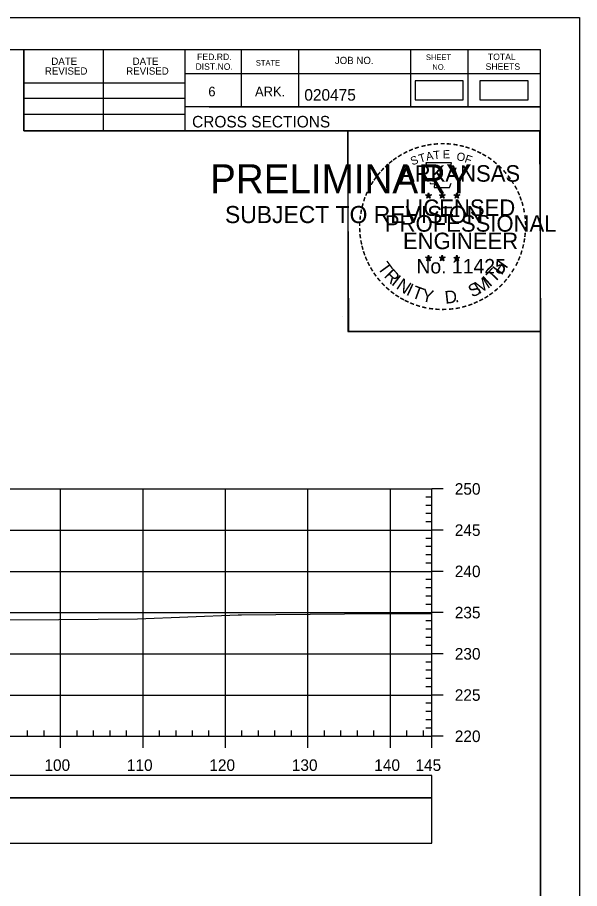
# Model space of a CAD drawing. Extents: x 1386544 to 1388153, y 379785 to 390999.
# Drawn here: x 1388085 to 1388153.2, y 384145.4 to 384251 of the extents above; entities that cross this region are included whole.
import ezdxf

# ---------------------------------------------------------------- set-up
doc = ezdxf.new("R2010")
doc.units = 0
for name, color, linetype in [('R_Axis', 7, 'Continuous'), ('R_Axis Annot', 7, 'Continuous'), ('R_Border', 7, 'Continuous'), ('R_Border PE', 7, 'Continuous'), ('R_Border Prem', 7, 'Continuous'), ('R_Exist Surface', 7, 'Continuous'), ('R_Grid', 7, 'Continuous'), ('R_No Plot', 7, 'Continuous'), ('S_SHOULDER', 7, 'Continuous')]:
    doc.layers.add(name, color=color, linetype=linetype)

msp = doc.modelspace()

# ---------------------------------------------------------------- linework, layer by layer
at = {"layer": 'R_Axis'}
for p, q in [((1388135.25, 384163.84), (1388135.25, 384193.84)), ((1388136.65, 384193.84), (1388135.25, 384193.84)), ((1388135.25, 384192.84), (1388134.55, 384192.84)), ((1388135.25, 384191.84), (1388134.55, 384191.84)), ((1388135.25, 384190.84), (1388134.55, 384190.84)), ((1388135.25, 384189.84), (1388134.55, 384189.84)), ((1388136.65, 384188.84), (1388135.25, 384188.84)), ((1388135.25, 384187.84), (1388134.55, 384187.84)), ((1388135.25, 384186.84), (1388134.55, 384186.84)), ((1388135.25, 384185.84), (1388134.55, 384185.84)), ((1388135.25, 384184.84), (1388134.55, 384184.84)), ((1388136.65, 384183.84), (1388135.25, 384183.84)), ((1388135.25, 384182.84), (1388134.55, 384182.84)), ((1388135.25, 384181.84), (1388134.55, 384181.84)), ((1388135.25, 384180.84), (1388134.55, 384180.84)), ((1388135.25, 384179.84), (1388134.55, 384179.84)), ((1388136.65, 384178.84), (1388135.25, 384178.84)), ((1388135.25, 384177.84), (1388134.55, 384177.84)), ((1388135.25, 384176.84), (1388134.55, 384176.84)), ((1388135.25, 384175.84), (1388134.55, 384175.84)), ((1388135.25, 384174.84), (1388134.55, 384174.84)), ((1388136.65, 384173.84), (1388135.25, 384173.84)), ((1388135.25, 384172.84), (1388134.55, 384172.84)), ((1388135.25, 384171.84), (1388134.55, 384171.84)), ((1388135.25, 384170.84), (1388134.55, 384170.84)), ((1388135.25, 384169.84), (1388134.55, 384169.84)), ((1388136.65, 384168.84), (1388135.25, 384168.84)), ((1388135.25, 384167.84), (1388134.55, 384167.84)), ((1388135.25, 384166.84), (1388134.55, 384166.84)), ((1388135.25, 384165.84), (1388134.55, 384165.84)), ((1388086.25, 384163.84), (1388086.25, 384164.54)), ((1388088.25, 384163.84), (1388088.25, 384164.54)), ((1388092.25, 384163.84), (1388092.25, 384164.54)), ((1388094.25, 384163.84), (1388094.25, 384164.54)), ((1388096.25, 384163.84), (1388096.25, 384164.54)), ((1388098.25, 384163.84), (1388098.25, 384164.54)), ((1388102.25, 384163.84), (1388102.25, 384164.54)), ((1388104.25, 384163.84), (1388104.25, 384164.54)), ((1388106.25, 384163.84), (1388106.25, 384164.54)), ((1388108.25, 384163.84), (1388108.25, 384164.54)), ((1388112.25, 384163.84), (1388112.25, 384164.54)), ((1388114.25, 384163.84), (1388114.25, 384164.54)), ((1388116.25, 384163.84), (1388116.25, 384164.54)), ((1388118.25, 384163.84), (1388118.25, 384164.54)), ((1388122.25, 384163.84), (1388122.25, 384164.54)), ((1388124.25, 384163.84), (1388124.25, 384164.54)), ((1388126.25, 384163.84), (1388126.25, 384164.54)), ((1388128.25, 384163.84), (1388128.25, 384164.54)), ((1388132.25, 384163.84), (1388132.25, 384164.54)), ((1388134.25, 384163.84), (1388134.25, 384164.54)), ((1388135.25, 384164.84), (1388134.55, 384164.84)), ((1387845.25, 384163.84), (1388135.25, 384163.84)), ((1388090.25, 384162.44), (1388090.25, 384163.84)), ((1388100.25, 384162.44), (1388100.25, 384163.84)), ((1388110.25, 384162.44), (1388110.25, 384163.84)), ((1388120.25, 384162.44), (1388120.25, 384163.84)), ((1388130.25, 384162.44), (1388130.25, 384163.84)), ((1388135.25, 384162.44), (1388135.25, 384163.84)), ((1388136.65, 384163.84), (1388135.25, 384163.84))]:
    msp.add_line(p, q, dxfattribs=at)
at = {"layer": 'R_Axis Annot'}
for points in [[(1388064.27, 384156.39), (1388135.25, 384156.39), (1388135.25, 384159.1), (1388064.27, 384159.1)], [(1388064.27, 384150.87), (1388135.25, 384150.87), (1388135.25, 384156.39), (1388064.27, 384156.39)]]:
    msp.add_lwpolyline(points, close=True, dxfattribs=at)
at = {"layer": 'R_Border'}
for p, q in [((1387832.25, 384247.13), (1388148.43, 384247.13)), ((1388085.79, 384237.25), (1388085.79, 384247.13)), ((1388095.47, 384237.25), (1388095.47, 384247.13)), ((1388105.33, 384247.13), (1388105.33, 384237.25)), ((1388112.17, 384247.13), (1388112.17, 384240.19)), ((1388119.11, 384247.13), (1388119.11, 384240.19)), ((1388132.69, 384247.13), (1388132.69, 384240.19)), ((1388139.63, 384247.13), (1388139.63, 384240.19)), ((1388148.43, 384041.67), (1388148.43, 384247.13)), ((1388148.43, 384244.19), (1388105.33, 384244.19)), ((1388148.43, 384244.21), (1388148.43, 384244.21)), ((1388085.79, 384243.11), (1388105.33, 384243.11)), ((1388085.79, 384241.25), (1388105.33, 384241.25)), ((1388148.43, 384240.19), (1388105.33, 384240.19)), ((1388108.29, 384240.19), (1388148.43, 384240.19)), ((1388085.79, 384239.31), (1388105.33, 384239.31)), ((1388148.43, 384237.25), (1388085.79, 384237.25))]:
    msp.add_line(p, q, dxfattribs=at)
at = {"layer": 'R_Border PE'}
for p, q in [((1388134.52, 384229.51), (1388134.87, 384229.39)), ((1388134.52, 384229.51), (1388134.77, 384229.46)), ((1388134.52, 384229.51), (1388134.75, 384229.38)), ((1388134.65, 384229.1), (1388134.87, 384229.39)), ((1388134.65, 384229.1), (1388134.78, 384229.34)), ((1388134.65, 384229.1), (1388134.86, 384229.31)), ((1388134.87, 384229.76), (1388134.82, 384229.51)), ((1388135.08, 384229.1), (1388134.86, 384229.31)), ((1388134.87, 384229.39), (1388134.87, 384229.76)), ((1388134.87, 384229.76), (1388134.91, 384229.51)), ((1388135.21, 384229.51), (1388134.87, 384229.39)), ((1388135.08, 384229.1), (1388134.87, 384229.39)), ((1388135.21, 384229.51), (1388134.93, 384229.46)), ((1388135.08, 384229.1), (1388134.94, 384229.39)), ((1388135.21, 384229.51), (1388135.01, 384229.4)), ((1388136.19, 384229.51), (1388136.54, 384229.39)), ((1388136.19, 384229.51), (1388136.44, 384229.46)), ((1388136.19, 384229.51), (1388136.42, 384229.38)), ((1388136.32, 384229.1), (1388136.54, 384229.39)), ((1388136.32, 384229.1), (1388136.45, 384229.34)), ((1388136.32, 384229.1), (1388136.53, 384229.31)), ((1388136.54, 384229.76), (1388136.49, 384229.51)), ((1388136.75, 384229.1), (1388136.53, 384229.31)), ((1388136.54, 384229.39), (1388136.54, 384229.76)), ((1388136.54, 384229.76), (1388136.58, 384229.51)), ((1388136.88, 384229.51), (1388136.54, 384229.39)), ((1388136.75, 384229.1), (1388136.54, 384229.39)), ((1388136.88, 384229.51), (1388136.6, 384229.46)), ((1388136.75, 384229.1), (1388136.61, 384229.39)), ((1388136.88, 384229.51), (1388136.68, 384229.4)), ((1388137.95, 384229.49), (1388138.3, 384229.38)), ((1388137.95, 384229.49), (1388138.2, 384229.45)), ((1388137.95, 384229.49), (1388138.19, 384229.37)), ((1388138.08, 384229.09), (1388138.3, 384229.38)), ((1388138.08, 384229.09), (1388138.21, 384229.33)), ((1388138.08, 384229.09), (1388138.3, 384229.3)), ((1388138.3, 384229.75), (1388138.26, 384229.5)), ((1388138.3, 384229.38), (1388138.3, 384229.75)), ((1388138.3, 384229.75), (1388138.35, 384229.5)), ((1388138.65, 384229.49), (1388138.3, 384229.38)), ((1388138.51, 384229.09), (1388138.3, 384229.38)), ((1388138.51, 384229.09), (1388138.3, 384229.3)), ((1388138.65, 384229.49), (1388138.36, 384229.44)), ((1388138.51, 384229.09), (1388138.38, 384229.38)), ((1388138.65, 384229.49), (1388138.44, 384229.39)), ((1388134.51, 384221.93), (1388134.86, 384221.82)), ((1388134.51, 384221.93), (1388134.77, 384221.89)), ((1388134.51, 384221.93), (1388134.75, 384221.81)), ((1388134.65, 384221.52), (1388134.86, 384221.82)), ((1388134.65, 384221.52), (1388134.77, 384221.77)), ((1388134.65, 384221.52), (1388134.86, 384221.74)), ((1388134.86, 384222.19), (1388134.82, 384221.93)), ((1388134.86, 384221.82), (1388134.86, 384222.19)), ((1388134.86, 384222.19), (1388134.91, 384221.94)), ((1388135.21, 384221.93), (1388134.86, 384221.82)), ((1388135.07, 384221.52), (1388134.86, 384221.82)), ((1388135.07, 384221.52), (1388134.86, 384221.74)), ((1388135.21, 384221.93), (1388134.92, 384221.88)), ((1388135.07, 384221.52), (1388134.94, 384221.82)), ((1388135.21, 384221.93), (1388135, 384221.83)), ((1388136.18, 384221.93), (1388136.53, 384221.82)), ((1388136.18, 384221.93), (1388136.43, 384221.89)), ((1388136.18, 384221.93), (1388136.42, 384221.81)), ((1388136.31, 384221.52), (1388136.53, 384221.82)), ((1388136.31, 384221.52), (1388136.44, 384221.77)), ((1388136.31, 384221.52), (1388136.53, 384221.74)), ((1388136.53, 384222.19), (1388136.49, 384221.93)), ((1388136.53, 384221.82), (1388136.53, 384222.19)), ((1388136.53, 384222.19), (1388136.58, 384221.94)), ((1388136.88, 384221.93), (1388136.53, 384221.82)), ((1388136.74, 384221.52), (1388136.53, 384221.82)), ((1388136.74, 384221.52), (1388136.53, 384221.74)), ((1388136.88, 384221.93), (1388136.59, 384221.88)), ((1388136.74, 384221.52), (1388136.61, 384221.82)), ((1388136.88, 384221.93), (1388136.67, 384221.83)), ((1388137.95, 384221.92), (1388138.3, 384221.81)), ((1388137.95, 384221.92), (1388138.2, 384221.88)), ((1388137.95, 384221.92), (1388138.19, 384221.8)), ((1388138.08, 384221.51), (1388138.3, 384221.81)), ((1388138.08, 384221.51), (1388138.21, 384221.76)), ((1388138.08, 384221.51), (1388138.3, 384221.73)), ((1388138.3, 384222.18), (1388138.26, 384221.92)), ((1388138.3, 384221.81), (1388138.3, 384222.18)), ((1388138.3, 384222.18), (1388138.35, 384221.93)), ((1388138.64, 384221.92), (1388138.3, 384221.81)), ((1388138.51, 384221.51), (1388138.3, 384221.81)), ((1388138.51, 384221.51), (1388138.3, 384221.73)), ((1388138.64, 384221.92), (1388138.36, 384221.87)), ((1388138.51, 384221.51), (1388138.37, 384221.81)), ((1388138.64, 384221.92), (1388138.44, 384221.82))]:
    msp.add_line(p, q, dxfattribs=at)
for points in [[(1388134.56, 384233.38), (1388134.83, 384232.56)], [(1388138.07, 384232.46), (1388138.21, 384232.75), (1388137.53, 384232.72), (1388137.67, 384233.38), (1388134.56, 384233.38)], [(1388135.05, 384230.96), (1388135.05, 384230.87), (1388135.61, 384230.85), (1388135.56, 384230.38), (1388137.43, 384230.38), (1388137.63, 384230.92)], [(1388134.87, 384229.76), (1388135.08, 384229.1), (1388134.52, 384229.51), (1388135.21, 384229.51), (1388134.65, 384229.1), (1388134.87, 384229.76)], [(1388136.54, 384229.76), (1388136.75, 384229.1), (1388136.19, 384229.51), (1388136.88, 384229.51), (1388136.32, 384229.1), (1388136.54, 384229.76)], [(1388138.3, 384229.75), (1388138.51, 384229.09), (1388137.95, 384229.49), (1388138.65, 384229.49), (1388138.08, 384229.09), (1388138.3, 384229.75)], [(1388134.86, 384222.19), (1388135.07, 384221.52), (1388134.51, 384221.93), (1388135.21, 384221.93), (1388134.65, 384221.52), (1388134.86, 384222.19)], [(1388136.53, 384222.19), (1388136.74, 384221.52), (1388136.18, 384221.93), (1388136.88, 384221.93), (1388136.31, 384221.52), (1388136.53, 384222.19)], [(1388138.3, 384222.18), (1388138.51, 384221.51), (1388137.95, 384221.92), (1388138.64, 384221.92), (1388138.08, 384221.51), (1388138.3, 384222.18)]]:
    msp.add_lwpolyline(points, dxfattribs=at)
for centre, radius in [((1388134.86, 384229.39), 0.172), ((1388134.86, 384229.39), 0.145), ((1388134.86, 384229.39), 0.116), ((1388134.86, 384229.39), 0.0991), ((1388134.86, 384229.39), 0.0747), ((1388134.86, 384229.39), 0.0495), ((1388134.86, 384229.39), 0.0296), ((1388136.53, 384229.39), 0.172), ((1388136.53, 384229.39), 0.145), ((1388136.53, 384229.39), 0.116), ((1388136.53, 384229.39), 0.0991), ((1388136.53, 384229.39), 0.0747), ((1388136.53, 384229.39), 0.0495), ((1388136.53, 384229.39), 0.0296), ((1388138.3, 384229.38), 0.172), ((1388138.3, 384229.38), 0.145), ((1388138.3, 384229.38), 0.116), ((1388138.3, 384229.38), 0.0991), ((1388138.3, 384229.38), 0.0747), ((1388138.3, 384229.38), 0.0495), ((1388138.3, 384229.38), 0.0296), ((1388134.86, 384221.82), 0.172), ((1388134.86, 384221.82), 0.145), ((1388134.86, 384221.82), 0.116), ((1388134.86, 384221.82), 0.0991), ((1388134.86, 384221.82), 0.0747), ((1388134.86, 384221.82), 0.0495), ((1388134.86, 384221.82), 0.0296), ((1388136.53, 384221.82), 0.172), ((1388136.53, 384221.82), 0.145), ((1388136.53, 384221.82), 0.116), ((1388136.53, 384221.82), 0.0991), ((1388136.53, 384221.82), 0.0747), ((1388136.53, 384221.82), 0.0495), ((1388136.53, 384221.82), 0.0296), ((1388138.3, 384221.81), 0.172), ((1388138.3, 384221.81), 0.145), ((1388138.3, 384221.81), 0.116), ((1388138.3, 384221.81), 0.0991), ((1388138.3, 384221.81), 0.0747), ((1388138.3, 384221.81), 0.0495), ((1388138.3, 384221.81), 0.0296)]:
    msp.add_circle(centre, radius, dxfattribs=at)
at = {"layer": 'R_Exist Surface'}
msp.add_lwpolyline([(1388029.98, 384177.1), (1388036.21, 384177.09), (1388046.32, 384177.31), (1388050.14, 384177.42), (1388054.94, 384177.54), (1388066.5, 384177.59), (1388067.74, 384177.62), (1388071.19, 384177.7), (1388080.1, 384177.92), (1388083.68, 384177.98), (1388090.04, 384178.02), (1388099.57, 384178.08), (1388111.78, 384178.56), (1388112.08, 384178.57), (1388112.19, 384178.57), (1388128.83, 384178.72), (1388131.01, 384178.74), (1388135.25, 384178.69)], dxfattribs=at)
at = {"layer": 'R_Grid'}
for p, q in [((1387845.25, 384193.84), (1388135.25, 384193.84)), ((1388090.25, 384163.84), (1388090.25, 384193.84)), ((1388100.25, 384163.84), (1388100.25, 384193.84)), ((1388110.25, 384163.84), (1388110.25, 384193.84)), ((1388120.25, 384163.84), (1388120.25, 384193.84)), ((1388130.25, 384163.84), (1388130.25, 384193.84)), ((1388135.25, 384163.84), (1388135.25, 384193.84)), ((1387845.25, 384188.84), (1388135.25, 384188.84)), ((1387845.25, 384183.84), (1388135.25, 384183.84)), ((1387845.25, 384178.84), (1388135.25, 384178.84)), ((1387845.25, 384173.84), (1388135.25, 384173.84)), ((1387845.25, 384168.84), (1388135.25, 384168.84)), ((1387845.25, 384163.84), (1388135.25, 384163.84))]:
    msp.add_line(p, q, dxfattribs=at)
at = {"layer": 'R_No Plot'}
for p, q in [((1387819.85, 384251.02), (1388153.18, 384251.02)), ((1388124.47, 384214.79), (1388124.47, 384214.79))]:
    msp.add_line(p, q, dxfattribs=at)
for points in [[(1387819.84, 384251.02), (1388153.18, 384251.02), (1388153.18, 384037.69), (1387819.84, 384037.69)], [(1388066.17, 384247.13), (1388085.79, 384247.13), (1388085.79, 384237.25), (1388101.9, 384237.25), (1388125.1, 384237.25), (1388125.1, 384212.92), (1388148.43, 384212.92), (1388148.43, 384041.67), (1387832.25, 384041.67), (1387832.25, 384247.13)], [(1388125.1, 384237.25), (1388148.31, 384237.25), (1388148.43, 384212.92), (1388125.22, 384212.92)]]:
    msp.add_lwpolyline(points, close=True, dxfattribs=at)
at = {"layer": 'S_SHOULDER'}
for points in [[(1388133.24, 384241.04), (1388139.08, 384241.04), (1388139.08, 384243.35), (1388133.24, 384243.35)], [(1388141.11, 384241.04), (1388146.95, 384241.04), (1388146.95, 384243.35), (1388141.11, 384243.35)]]:
    msp.add_lwpolyline(points, close=True, dxfattribs=at)

# ---------------------------------------------------------------- texts
at = {"layer": 'R_Axis Annot'}
for s, p in [('250', (1388138.05, 384193.14)), ('245', (1388138.05, 384188.14)), ('240', (1388138.05, 384183.14)), ('235', (1388138.05, 384178.14)), ('230', (1388138.05, 384173.14)), ('225', (1388138.05, 384168.14)), ('220', (1388138.05, 384163.14)), ('100', (1388088.29, 384159.64)), ('110', (1388098.29, 384159.64)), ('120', (1388108.29, 384159.64)), ('130', (1388118.29, 384159.64)), ('140', (1388128.29, 384159.64)), ('145', (1388133.28, 384159.64))]:
    msp.add_text(s, height=1.4, dxfattribs=at).set_placement(p)
at = {"layer": 'R_Border'}
for s, height, p in [('DATE', 0.879, (1388089.13, 384245.27)), ('DATE', 0.879, (1388098.99, 384245.27)), ('FED.RD.', 0.782, (1388106.81, 384245.85)), ('STATE', 0.684, (1388113.93, 384245.17)), ('JOB NO.', 0.879, (1388123.51, 384245.37)), ('SHEET', 0.684, (1388134.55, 384245.85)), ('TOTAL', 0.782, (1388142.07, 384245.85)), ('REVISED', 0.879, (1388088.35, 384244.09)), ('REVISED', 0.879, (1388098.21, 384244.09)), ('DIST.NO.', 0.782, (1388106.61, 384244.67)), ('NO.', 0.684, (1388135.33, 384244.67)), ('SHEETS', 0.782, (1388141.79, 384244.67)), ('6', 1.17, (1388108.17, 384241.45)), ('ARK.', 1.172, (1388113.83, 384241.45)), ('020475', 1.4, (1388119.81, 384240.93)), ('CROSS SECTIONS', 1.4, (1388106.2, 384237.68))]:
    msp.add_text(s, height=height, rotation=360, dxfattribs=at).set_placement(p)
at = {"layer": 'R_Border PE'}
for s, height, rotation, p in [('-', 1.6, 24.3072, (1388132.67, 384234.24)), ('-', 1.6, 19.1761, (1388133.31, 384234.51)), ('-', 1.6, 13.6301, (1388134.06, 384234.75)), ('-', 1.6, 10.2193, (1388134.73, 384234.91)), ('-', 1.6, 5.8968, (1388135.46, 384235.02)), ('-', 1.6, 0.1862, (1388136.23, 384235.1)), ('-', 1.6, 357.743, (1388136.96, 384235.08)), ('-', 1.6, 352.1617, (1388137.7, 384235.03)), ('-', 1.6, 347.2049, (1388138.42, 384234.91)), ('-', 1.6, 342.3362, (1388139.06, 384234.76)), ('-', 1.6, 337.8551, (1388139.79, 384234.53)), ('-', 1.6, 36.2317, (1388130.86, 384233.16)), ('-', 1.6, 34.0636, (1388131.44, 384233.55)), ('-', 1.6, 28.7918, (1388132.04, 384233.92)), ('S', 1, 21.594, (1388132.91, 384233.06)), ('T', 1, 16.4036, (1388133.83, 384233.39)), ('A', 1, 11.2132, (1388134.65, 384233.64)), ('T', 1, 6.0228, (1388135.5, 384233.81)), ('E', 1, 0.8323, (1388136.61, 384233.92)), ('O', 1, 350.4515, (1388138.21, 384233.71)), ('F', 1, 340.0707, (1388139.16, 384233.48)), ('-', 1.6, 334.1211, (1388140.42, 384234.26)), ('-', 1.6, 329.6409, (1388141, 384233.98)), ('-', 1.6, 325.8627, (1388141.64, 384233.62)), ('-', 1.6, 42.9622, (1388129.95, 384232.36)), ('-', 1.6, 38.9507, (1388130.39, 384232.78)), ('ARKANSAS', 2, 360, (1388131.41, 384231.1)), ('-', 1.6, 320.5297, (1388142.25, 384233.19)), ('-', 1.6, 315.5786, (1388142.85, 384232.71)), ('-', 1.6, 50.6142, (1388129.1, 384231.4)), ('-', 1.6, 48.423, (1388129.51, 384231.89)), ('-', 1.6, 309.8797, (1388143.42, 384232.16)), ('-', 1.6, 58.0706, (1388128.37, 384230.31)), ('-', 1.6, 54.2325, (1388128.69, 384230.83)), ('-', 1.6, 306.6522, (1388143.95, 384231.55)), ('-', 1.4, 303.6753, (1388144.43, 384230.99)), ('-', 1.6, 67.7743, (1388127.79, 384229.08)), ('-', 1.6, 62.8713, (1388128.05, 384229.69)), ('-', 1.6, 299.6684, (1388144.75, 384230.38)), ('-', 1.6, 294.6628, (1388145.08, 384229.77)), ('-', 1.6, 72.3945, (1388127.57, 384228.45)), ('LICENSED', 2, 360, (1388132.01, 384226.95)), ('DWB', 0.01, 360, (1388134.85, 384229.39)), ('DWB', 0.01, 360, (1388136.52, 384229.39)), ('DWB', 0.01, 360, (1388138.29, 384229.38)), ('-', 1.6, 290.5728, (1388145.33, 384229.19)), ('-', 1.6, 81.2013, (1388127.25, 384227.02)), ('-', 1.6, 75.461, (1388127.38, 384227.74)), ('-', 1.6, 285.1233, (1388145.57, 384228.61)), ('-', 1.6, 280.5493, (1388145.77, 384227.87)), ('-', 1.6, 85.1863, (1388127.17, 384226.33)), ('PROFESSIONAL', 2, 360, (1388129.58, 384225.04)), ('-', 1.6, 276.5962, (1388145.93, 384227.1)), ('-', 1.6, 89.0622, (1388127.14, 384225.63)), ('-', 1.6, 274.3301, (1388145.99, 384226.38)), ('-', 1.6, 269.9407, (1388146.02, 384225.75)), ('-', 1.6, 94.1959, (1388127.18, 384224.91)), ('-', 1.6, 98.9479, (1388127.25, 384224.24)), ('ENGINEER', 2, 360, (1388131.77, 384222.92)), ('-', 1.6, 263.5172, (1388146, 384225.08)), ('-', 1.6, 101.7149, (1388127.39, 384223.51)), ('-', 1.6, 255.7626, (1388145.82, 384223.75)), ('-', 1.6, 260.9953, (1388145.93, 384224.43)), ('-', 1.6, 105.4578, (1388127.55, 384222.91)), ('-', 1.6, 109.0874, (1388127.76, 384222.28)), ('-', 1.6, 252.8681, (1388145.64, 384223.03)), ('-', 1.6, 114.0643, (1388128.02, 384221.69)), ('-', 1.6, 115.7289, (1388128.32, 384221.07)), ('T', 1.54, 306.0406, (1388128.62, 384220.66)), ('No. 11425', 1.757, 360, (1388133.4, 384219.97)), ('DWB', 0.01, 360, (1388134.85, 384221.82)), ('DWB', 0.01, 360, (1388136.52, 384221.82)), ('DWB', 0.01, 360, (1388138.28, 384221.81)), ('H', 1.54, 54.6088, (1388143.74, 384219.69)), ('-', 1.6, 244.6197, (1388145.16, 384221.73)), ('-', 1.6, 247.8887, (1388145.42, 384222.35)), ('-', 1.6, 120.4471, (1388128.68, 384220.48)), ('R', 1.54, 314.005, (1388129.38, 384219.61)), ('T', 1.54, 46.6444, (1388142.85, 384218.75)), ('-', 1.6, 239.0712, (1388144.76, 384220.97)), ('-', 1.6, 125.8934, (1388129.08, 384219.92)), ('-', 1.6, 130.7181, (1388129.54, 384219.37)), ('I', 1.54, 321.9694, (1388130.28, 384218.68)), ('N', 1.54, 326.5002, (1388130.85, 384218.21)), ('M', 1.54, 32.6563, (1388141.01, 384217.43)), ('I', 1.54, 42.1136, (1388142.29, 384218.27)), ('-', 1.6, 231.2538, (1388143.93, 384219.75)), ('-', 1.6, 233.8452, (1388144.36, 384220.32)), ('-', 1.6, 134.2238, (1388130.06, 384218.82)), ('-', 1.6, 138.9338, (1388130.59, 384218.36)), ('I', 1.54, 335.3603, (1388132.06, 384217.42)), ('T', 1.54, 339.8912, (1388132.72, 384217.09)), ('S', 1.54, 26.9312, (1388140.17, 384217.02)), ('-', 1.6, 221.0851, (1388142.93, 384218.68)), ('-', 1.6, 225.7653, (1388143.45, 384219.19)), ('-', 1.6, 144.6463, (1388131.14, 384217.95)), ('-', 1.6, 148.0898, (1388131.7, 384217.58)), ('Y', 1.54, 347.8556, (1388133.94, 384216.65)), ('D', 1.54, 6.3969, (1388136.92, 384216.29)), ('-', 1.6, 212.2491, (1388141.85, 384217.82)), ('-', 1.6, 215.7363, (1388142.38, 384218.21)), ('-', 1.6, 151.5704, (1388132.28, 384217.26)), ('-', 1.6, 154.6002, (1388132.8, 384217.01)), ('-', 1.6, 158.5612, (1388133.43, 384216.76)), ('-', 1.6, 162.7983, (1388134.12, 384216.54)), ('.', 1.54, 13.7642, (1388138.11, 384216.42)), ('-', 1.6, 195.4743, (1388139.37, 384216.64)), ('-', 1.6, 200.7184, (1388140.05, 384216.88)), ('-', 1.6, 204.2516, (1388140.66, 384217.16)), ('-', 1.6, 207.3568, (1388141.29, 384217.48)), ('-', 1.6, 167.5555, (1388134.83, 384216.38)), ('-', 1.6, 173.1155, (1388135.6, 384216.27)), ('-', 1.6, 176.5183, (1388136.35, 384216.22)), ('-', 1.6, 181.5918, (1388137.09, 384216.24)), ('-', 1.6, 185.8167, (1388137.9, 384216.31)), ('-', 1.6, 191.2858, (1388138.64, 384216.44))]:
    msp.add_text(s, height=height, rotation=rotation, dxfattribs=at).set_placement(p)
at = {"layer": 'R_Border Prem'}
for s, height, p in [('PRELIMINARY', 3.5, (1388108.38, 384229.71)), ('DWB', 0.01, (1388109.13, 384231.56)), ('SUBJECT TO REVISION', 2.0751, (1388110.19, 384226.08))]:
    msp.add_text(s, height=height, rotation=360, dxfattribs=at).set_placement(p)

doc.saveas('drawing.dxf')
